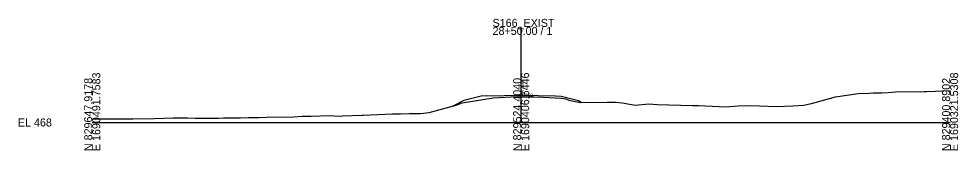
# Model space of a CAD drawing. Extents: x 1621104 to 1621433, y 1192880 to 1199414.
# Drawn here: x 1621104.2 to 1621432.7, y 1194379.5 to 1194425.5 of the extents above; entities that cross this region are included whole.
import ezdxf

# ---------------------------------------------------------------- set-up
doc = ezdxf.new("R2010")
doc.units = 0
for name, color, linetype in [('RD_GPK_XS_Cell', 7, 'Continuous'), ('RD_XS_EarthShd', 7, 'Continuous'), ('RD_XS_ExGround', 7, 'Continuous'), ('RD_XS_Pave', 7, 'Continuous'), ('RD_XS_TieSlope', 7, 'Continuous'), ('RD_XS_TX_Elev_EX', 7, 'Continuous'), ('RD_XS_TX_Elev_PR', 7, 'Continuous')]:
    doc.layers.add(name, color=color, linetype=linetype)

msp = doc.modelspace()

# ---------------------------------------------------------------- linework, layer by layer
at = {"layer": 'RD_GPK_XS_Cell'}
for p, q in [((1621279.86, 1194389.24), (1621279.86, 1194422.68)), ((1621129.86, 1194389.24), (1621279.86, 1194389.24)), ((1621279.86, 1194389.24), (1621429.86, 1194389.24))]:
    msp.add_line(p, q, dxfattribs=at)
at = {"layer": 'RD_XS_EarthShd'}
for p, q in [((1621267.86, 1194398.59), (1621265.86, 1194398.43)), ((1621291.86, 1194398.59), (1621293.86, 1194398.43))]:
    msp.add_line(p, q, dxfattribs=at)
at = {"layer": 'RD_XS_ExGround'}
msp.add_lwpolyline([(1621129.86, 1194390.43), (1621132.31, 1194390.52), (1621132.86, 1194390.53), (1621133.97, 1194390.53), (1621141.8, 1194390.53), (1621144.04, 1194390.55), (1621151.66, 1194390.66), (1621158.13, 1194390.82), (1621160.8, 1194390.88), (1621163.13, 1194390.84), (1621165.85, 1194390.74), (1621174.04, 1194390.8), (1621175.75, 1194390.85), (1621181.74, 1194390.93), (1621184.44, 1194390.95), (1621188, 1194391.04), (1621190.78, 1194391.08), (1621200.2, 1194391.26), (1621203.39, 1194391.43), (1621206.46, 1194391.5), (1621212.85, 1194391.71), (1621214.49, 1194391.55), (1621216.76, 1194391.5), (1621217.43, 1194391.54), (1621224.21, 1194391.83), (1621224.59, 1194391.85), (1621234.88, 1194392.29), (1621237.65, 1194392.27), (1621240.81, 1194392.37), (1621244.63, 1194392.43), (1621247.72, 1194392.69), (1621257.11, 1194395.25), (1621259.26, 1194396.13), (1621270.04, 1194397.91), (1621278.5, 1194398.28), (1621279.86, 1194398.25), (1621282.95, 1194398.21), (1621284.28, 1194398.17), (1621287.56, 1194398.06), (1621293.82, 1194397.79), (1621295.48, 1194397.54), (1621296.55, 1194397.04), (1621300.59, 1194396.29), (1621309.97, 1194396.33), (1621312.83, 1194396.35), (1621315.18, 1194396.17), (1621319.77, 1194395.32), (1621324.52, 1194395.72), (1621327.39, 1194395.51), (1621339.72, 1194395.24), (1621340.86, 1194395.2), (1621341.35, 1194395.19), (1621341.91, 1194395.17), (1621351.47, 1194394.74), (1621355.7, 1194395.08), (1621359.59, 1194395.14), (1621363.16, 1194395.04), (1621369.14, 1194394.78), (1621374.81, 1194395.06), (1621378.55, 1194395.3), (1621381.44, 1194395.86), (1621382.68, 1194396.23), (1621389.83, 1194398.2), (1621397.76, 1194399.43), (1621401.6, 1194399.52), (1621402.96, 1194399.56), (1621405.96, 1194399.67), (1621408.23, 1194399.77), (1621410.81, 1194399.93), (1621420.75, 1194400.1), (1621421.59, 1194400.12), (1621424.67, 1194400.2), (1621429.86, 1194400.38)], dxfattribs=at)
at = {"layer": 'RD_XS_Pave'}
for p, q in [((1621267.86, 1194398.59), (1621279.86, 1194398.83)), ((1621279.86, 1194398.83), (1621291.86, 1194398.59))]:
    msp.add_line(p, q, dxfattribs=at)
at = {"layer": 'RD_XS_TieSlope'}
for p, q in [((1621259.86, 1194396.93), (1621255.77, 1194394.89)), ((1621265.86, 1194398.43), (1621259.86, 1194396.93)), ((1621293.86, 1194398.43), (1621299.86, 1194396.93)), ((1621299.86, 1194396.93), (1621301.13, 1194396.29))]:
    msp.add_line(p, q, dxfattribs=at)

# ---------------------------------------------------------------- texts
at = {"layer": 'RD_GPK_XS_Cell'}
for s, p in [('S166_EXIST', (1621269.86, 1194422.68)), ('28+50.00 / 1', (1621269.86, 1194419.88)), ('EL 468', (1621103.86, 1194387.84))]:
    msp.add_text(s, height=2.8, dxfattribs=at).set_placement(p)
for s, p in [('E 1690491.7583', (1621132.66, 1194379.24)), ('E 1690406.6446', (1621282.66, 1194379.24)), ('E 1690321.5308', (1621432.66, 1194379.24)), ('N 829647.9178', (1621129.86, 1194379.24)), ('N 829524.4040', (1621279.86, 1194379.24)), ('N 829400.8902', (1621429.86, 1194379.24))]:
    msp.add_text(s, height=2.8, rotation=90, dxfattribs=at).set_placement(p)
at = {"layer": 'RD_XS_TX_Elev_EX'}
msp.add_text('477.02', height=1, dxfattribs=at).set_placement((1621279.76, 1194398.35))
at = {"layer": 'RD_XS_TX_Elev_PR'}
msp.add_text(' 477.59', height=1, rotation=90, dxfattribs=at).set_placement((1621280.86, 1194398.83))

doc.saveas('drawing.dxf')
